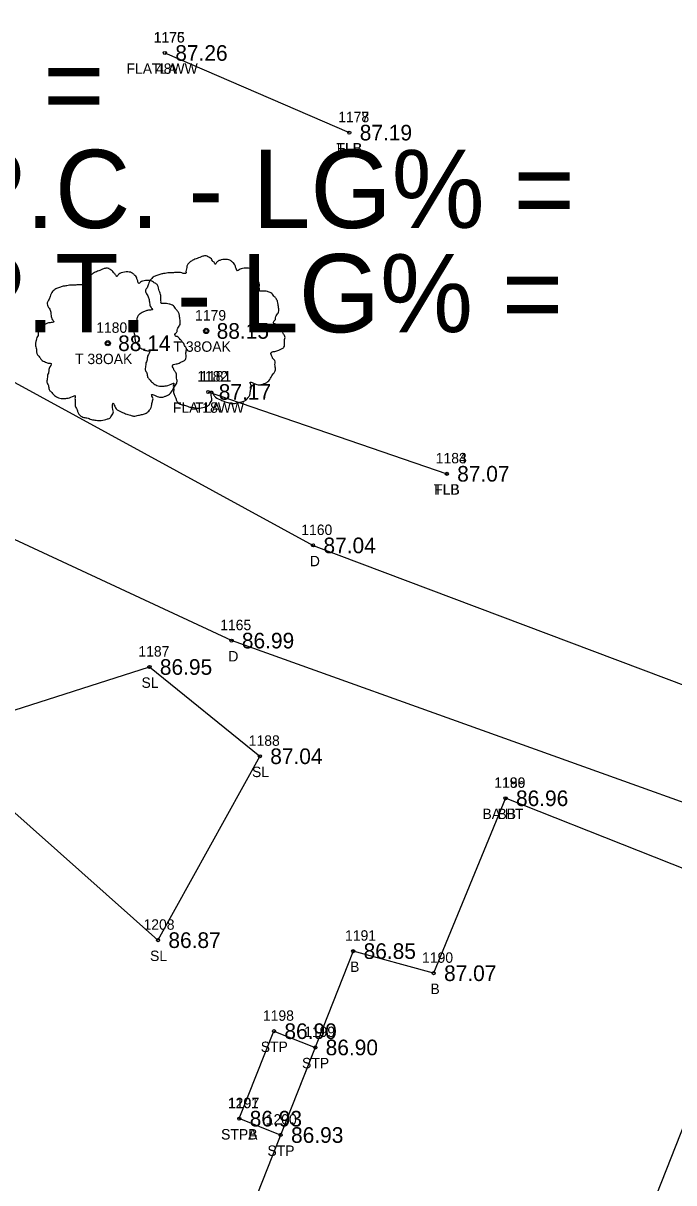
# Model space of a CAD drawing. Extents: x 2139392 to 2143384, y 505395 to 510520.
# Drawn here: x 2141405.4 to 2141467.9, y 510076.4 to 510187.6 of the extents above; entities that cross this region are included whole.
import ezdxf

# ---------------------------------------------------------------- set-up
doc = ezdxf.new("R2010")
doc.units = 0
for name, color, linetype in [('RD_EX_Bldg', 7, 'Continuous'), ('RD_EX_Bldg_txCode', 7, 'Continuous'), ('RD_EX_Conc', 7, 'Continuous'), ('RD_EX_Conc_txCode', 7, 'Continuous'), ('RD_EX_Driveway', 7, 'Continuous'), ('RD_EX_Driveway_txCode', 7, 'Continuous'), ('RD_EX_Fence_Other', 7, 'Continuous'), ('RD_EX_Fence_Other_txCode', 7, 'Continuous'), ('RD_EX_TX_Bldg_ELEV', 7, 'Continuous'), ('RD_EX_TX_Conc_ELEV', 7, 'Continuous'), ('RD_EX_TX_Driveway_ELEV', 7, 'Continuous'), ('RD_EX_TX_Fence_Other_ELEV', 7, 'Continuous'), ('RD_EX_TX_VEG_ELEV', 7, 'Continuous'), ('RD_EX_VEG', 7, 'Continuous'), ('RD_EX_VEG_txCode', 7, 'Continuous'), ('RD_HC_Cl', 7, 'Continuous'), ('RD_HC_Data', 7, 'Continuous'), ('RD_SMD_Locator', 7, 'Continuous')]:
    doc.layers.add(name, color=color, linetype=linetype)

msp = doc.modelspace()

# ---------------------------------------------------------------- linework, layer by layer
at = {"layer": 'RD_EX_Bldg'}
msp.add_lwpolyline([(2141451.72, 510113.31), (2141444.82, 510096.53), (2141437.1, 510098.65), (2141426.42, 510071.61), (2141433.86, 510068.13), (2141459.35, 510057.93), (2141477.25, 510103.22), (2141451.72, 510113.31)], dxfattribs=at)
at = {"layer": 'RD_EX_Conc'}
msp.add_lwpolyline([(2141426.17, 510082.58), (2141429.5, 510090.97), (2141433.46, 510089.41), (2141430.14, 510081.01), (2141426.17, 510082.58)], dxfattribs=at)
at = {"layer": 'RD_EX_Driveway'}
for points in [[(2141397.35, 510157.14), (2141433.25, 510137.56), (2141478.15, 510120.63)], [(2141480.37, 510108.75), (2141425.42, 510128.43), (2141389.73, 510145.03)]]:
    msp.add_lwpolyline(points, dxfattribs=at)
at = {"layer": 'RD_EX_Fence_Other'}
for p, q in [((2141419.03, 510184.79), (2141436.73, 510177.15)), ((2141423.2, 510152.28), (2141446.08, 510144.43))]:
    msp.add_line(p, q, dxfattribs=at)
at = {"layer": 'RD_EX_VEG'}
for p, q in [((2141419.03, 510184.79), (2141436.73, 510177.15)), ((2141423.2, 510152.28), (2141446.08, 510144.43))]:
    msp.add_line(p, q, dxfattribs=at)
msp.add_lwpolyline([(2141396.46, 510119.18), (2141417.55, 510125.9), (2141428.14, 510117.34), (2141418.37, 510099.7), (2141396.46, 510119.18)], dxfattribs=at)
for centre, radius in [((2141423, 510158.13), 0.25), ((2141422.98, 510158.12), 0.0001), ((2141413.55, 510156.95), 0.25), ((2141413.53, 510156.93), 0.0001)]:
    msp.add_circle(centre, radius, dxfattribs=at)
for points in [[(2141423.13, 510165.3), (2141422.83, 510165.33), (2141422.5, 510165.23), (2141422.25, 510165.13), (2141422.03, 510165.05), (2141421.8, 510164.95), (2141421.5, 510164.78), (2141421.28, 510164.58), (2141421.15, 510164.33), (2141421.1, 510164.1), (2141421.05, 510163.83), (2141421.05, 510163.65), (2141420.93, 510163.63), (2141420.78, 510163.65), (2141420.53, 510163.73), (2141420.28, 510163.73), (2141420.03, 510163.73), (2141419.68, 510163.7), (2141419.33, 510163.7), (2141419.05, 510163.65), (2141418.73, 510163.6), (2141418.35, 510163.48), (2141418, 510163.35), (2141417.7, 510163.1), (2141417.45, 510162.63), (2141417.33, 510162.28), (2141417.18, 510162.03), (2141417.33, 510161.58), (2141417.5, 510161.23), (2141417.53, 510161.03), (2141417.6, 510160.6), (2141417.7, 510160.38), (2141417.83, 510160.18), (2141417.75, 510160.15), (2141417.38, 510160.1), (2141417.08, 510160), (2141416.65, 510159.78), (2141416.43, 510159.55), (2141416.33, 510159.23), (2141416.3, 510158.88), (2141416.21, 510158.68), (2141416.13, 510158.4), (2141416.11, 510158.33), (2141416.06, 510158), (2141416.16, 510157.55), (2141416.18, 510157.2), (2141416.3, 510156.98), (2141416.45, 510156.8), (2141416.63, 510156.55), (2141417.03, 510156.33), (2141417.35, 510156.23), (2141417.55, 510156.21), (2141417.38, 510155.71), (2141417.33, 510155.36), (2141417.2, 510154.96), (2141417.2, 510154.88), (2141417.15, 510154.41), (2141417.3, 510154.08), (2141417.38, 510153.71), (2141417.55, 510153.48), (2141417.83, 510153.18), (2141418.15, 510152.96), (2141418.65, 510152.83), (2141419.05, 510152.86), (2141419.63, 510153.03), (2141419.88, 510153.11), (2141419.85, 510152.93), (2141419.88, 510152.56), (2141419.88, 510152.13), (2141420.03, 510151.81), (2141420.13, 510151.53), (2141420.28, 510151.28), (2141420.6, 510151.06), (2141421, 510150.98), (2141421.43, 510150.83), (2141421.88, 510150.76), (2141422.38, 510150.73), (2141422.98, 510150.88), (2141423.25, 510151.01), (2141423.35, 510151.18), (2141423.55, 510151.56), (2141423.5, 510151.78), (2141423.53, 510152.38), (2141423.63, 510152.21), (2141423.8, 510151.86), (2141424.3, 510151.56), (2141424.7, 510151.38), (2141425.18, 510151.23), (2141425.48, 510151.16), (2141425.95, 510151.23), (2141426.33, 510151.31), (2141426.7, 510151.43), (2141427, 510151.71), (2141427.18, 510151.98), (2141427.23, 510152.26), (2141427.3, 510152.63), (2141427.35, 510152.81)], [(2141427.35, 510152.81), (2141427.28, 510152.98), (2141427.23, 510153.23), (2141427.3, 510153.21), (2141427.48, 510153.16), (2141427.75, 510153.03), (2141427.97, 510152.96), (2141428.3, 510152.98), (2141428.57, 510153.08), (2141429.02, 510153.36), (2141429.3, 510153.83), (2141429.57, 510154.23), (2141429.65, 510154.56), (2141429.6, 510154.78), (2141429.57, 510155.28), (2141429.37, 510155.53), (2141429.32, 510155.66), (2141429.22, 510156.06), (2141429.3, 510156.11), (2141429.57, 510156.16), (2141429.95, 510156.28), (2141430.22, 510156.4), (2141430.45, 510156.58), (2141430.52, 510156.8), (2141430.5, 510157.2), (2141430.55, 510157.6), (2141430.47, 510157.75), (2141430.37, 510157.9), (2141430.3, 510158.1), (2141430.15, 510158.25), (2141430.05, 510158.4), (2141429.95, 510158.5), (2141429.82, 510158.65), (2141429.65, 510158.78), (2141429.5, 510158.83), (2141429.45, 510158.98), (2141429.6, 510159.18), (2141429.65, 510159.28), (2141429.67, 510159.5), (2141429.9, 510159.85), (2141429.95, 510160.25), (2141429.9, 510160.68), (2141429.85, 510160.95), (2141429.7, 510161.23), (2141429.5, 510161.48), (2141429.37, 510161.65), (2141429.2, 510161.78), (2141428.87, 510161.9), (2141428.62, 510161.95), (2141428.27, 510161.95), (2141428.07, 510162), (2141428.1, 510162.05), (2141428.1, 510162.2), (2141428.1, 510162.48), (2141428.02, 510162.93), (2141427.87, 510163.43), (2141427.87, 510163.45), (2141427.77, 510163.7), (2141427.55, 510163.9), (2141427.38, 510164), (2141427.18, 510164.13), (2141426.93, 510164.15), (2141426.63, 510164.15), (2141426.35, 510164.1), (2141426.15, 510164), (2141425.98, 510163.88), (2141425.9, 510164.03), (2141425.8, 510164.33), (2141425.75, 510164.48), (2141425.6, 510164.65), (2141425.38, 510164.85), (2141424.93, 510164.98), (2141424.3, 510164.9), (2141424, 510164.7), (2141423.85, 510164.53), (2141423.8, 510164.65), (2141423.6, 510164.85), (2141423.5, 510165.03), (2141423.33, 510165.15), (2141423.18, 510165.25), (2141423.08, 510165.3)], [(2141413.68, 510164.11), (2141413.38, 510164.14), (2141413.05, 510164.04), (2141412.8, 510163.94), (2141412.58, 510163.86), (2141412.35, 510163.76), (2141412.05, 510163.59), (2141411.83, 510163.39), (2141411.7, 510163.14), (2141411.65, 510162.91), (2141411.6, 510162.64), (2141411.6, 510162.46), (2141411.48, 510162.44), (2141411.33, 510162.46), (2141411.08, 510162.54), (2141410.83, 510162.54), (2141410.58, 510162.54), (2141410.23, 510162.51), (2141409.88, 510162.51), (2141409.61, 510162.46), (2141409.28, 510162.41), (2141408.91, 510162.29), (2141408.56, 510162.16), (2141408.26, 510161.91), (2141408.01, 510161.44), (2141407.88, 510161.09), (2141407.73, 510160.84), (2141407.88, 510160.39), (2141408.06, 510160.04), (2141408.08, 510159.84), (2141408.16, 510159.41), (2141408.26, 510159.19), (2141408.38, 510158.99), (2141408.31, 510158.96), (2141407.93, 510158.91), (2141407.63, 510158.81), (2141407.21, 510158.59), (2141406.98, 510158.37), (2141406.88, 510158.04), (2141406.86, 510157.69), (2141406.76, 510157.49), (2141406.68, 510157.22), (2141406.66, 510157.14), (2141406.61, 510156.82), (2141406.71, 510156.37), (2141406.73, 510156.02), (2141406.86, 510155.79), (2141407.01, 510155.62), (2141407.18, 510155.37), (2141407.58, 510155.14), (2141407.91, 510155.04), (2141408.11, 510155.02), (2141407.93, 510154.52), (2141407.88, 510154.17), (2141407.76, 510153.77), (2141407.76, 510153.69), (2141407.71, 510153.22), (2141407.86, 510152.89), (2141407.93, 510152.52), (2141408.11, 510152.29), (2141408.38, 510151.99), (2141408.71, 510151.77), (2141409.21, 510151.64), (2141409.61, 510151.67), (2141410.18, 510151.84), (2141410.43, 510151.92), (2141410.41, 510151.74), (2141410.43, 510151.37), (2141410.43, 510150.94), (2141410.58, 510150.62), (2141410.68, 510150.34), (2141410.83, 510150.09), (2141411.15, 510149.87), (2141411.55, 510149.79), (2141411.98, 510149.64), (2141412.43, 510149.57), (2141412.93, 510149.54), (2141413.53, 510149.69), (2141413.8, 510149.82), (2141413.9, 510149.99), (2141414.1, 510150.37), (2141414.05, 510150.59), (2141414.08, 510151.19), (2141414.18, 510151.02), (2141414.35, 510150.67), (2141414.85, 510150.37), (2141415.25, 510150.19), (2141415.73, 510150.04), (2141416.03, 510149.97), (2141416.5, 510150.04), (2141416.88, 510150.12), (2141417.25, 510150.24), (2141417.55, 510150.52), (2141417.73, 510150.79), (2141417.78, 510151.07), (2141417.85, 510151.44), (2141417.9, 510151.62)], [(2141417.9, 510151.62), (2141417.83, 510151.79), (2141417.78, 510152.04), (2141417.85, 510152.02), (2141418.03, 510151.97), (2141418.3, 510151.84), (2141418.53, 510151.77), (2141418.85, 510151.79), (2141419.13, 510151.89), (2141419.58, 510152.17), (2141419.85, 510152.64), (2141420.13, 510153.04), (2141420.2, 510153.37), (2141420.15, 510153.59), (2141420.13, 510154.09), (2141419.93, 510154.34), (2141419.88, 510154.47), (2141419.78, 510154.87), (2141419.85, 510154.92), (2141420.13, 510154.97), (2141420.5, 510155.09), (2141420.78, 510155.22), (2141421, 510155.39), (2141421.08, 510155.62), (2141421.05, 510156.02), (2141421.1, 510156.42), (2141421.03, 510156.57), (2141420.93, 510156.72), (2141420.85, 510156.92), (2141420.7, 510157.07), (2141420.6, 510157.22), (2141420.5, 510157.32), (2141420.38, 510157.47), (2141420.2, 510157.59), (2141420.05, 510157.64), (2141420, 510157.79), (2141420.15, 510157.99), (2141420.2, 510158.09), (2141420.23, 510158.32), (2141420.45, 510158.66), (2141420.5, 510159.06), (2141420.45, 510159.49), (2141420.4, 510159.76), (2141420.25, 510160.04), (2141420.05, 510160.29), (2141419.93, 510160.46), (2141419.75, 510160.59), (2141419.43, 510160.71), (2141419.18, 510160.76), (2141418.83, 510160.76), (2141418.63, 510160.81), (2141418.65, 510160.86), (2141418.65, 510161.01), (2141418.65, 510161.29), (2141418.58, 510161.74), (2141418.43, 510162.24), (2141418.43, 510162.26), (2141418.33, 510162.51), (2141418.1, 510162.71), (2141417.93, 510162.81), (2141417.73, 510162.94), (2141417.48, 510162.96), (2141417.18, 510162.96), (2141416.9, 510162.91), (2141416.7, 510162.81), (2141416.53, 510162.69), (2141416.45, 510162.84), (2141416.35, 510163.14), (2141416.3, 510163.29), (2141416.15, 510163.46), (2141415.93, 510163.66), (2141415.48, 510163.79), (2141414.85, 510163.71), (2141414.55, 510163.51), (2141414.4, 510163.34), (2141414.35, 510163.46), (2141414.15, 510163.66), (2141414.05, 510163.84), (2141413.88, 510163.96), (2141413.73, 510164.06), (2141413.63, 510164.11)]]:
    msp.add_spline(points, degree=3, dxfattribs=at)
at = {"layer": 'RD_HC_Cl'}
msp.add_arc((2138642.96, 511065.46), 2864.78, 339.91581, 348.5415, dxfattribs=at)
at = {"layer": 'RD_SMD_Locator'}
for centre in [(2141419.03, 510184.79), (2141419.03, 510184.79), (2141436.73, 510177.15), (2141436.73, 510177.15), (2141423, 510158.13), (2141413.55, 510156.95), (2141423.2, 510152.28), (2141423.2, 510152.28), (2141446.08, 510144.43), (2141446.08, 510144.43), (2141433.25, 510137.56), (2141425.42, 510128.43), (2141417.55, 510125.9), (2141428.14, 510117.34), (2141451.72, 510113.31), (2141451.72, 510113.31), (2141418.37, 510099.7), (2141437.1, 510098.65), (2141444.82, 510096.53), (2141429.5, 510090.97), (2141433.46, 510089.41), (2141426.17, 510082.58), (2141426.17, 510082.58), (2141430.14, 510081.01)]:
    msp.add_circle(centre, 0.15, dxfattribs=at)

# ---------------------------------------------------------------- texts
at = {"layer": 'RD_EX_Bldg_txCode'}
for s, p in [('1196', (2141450.63, 510114.31)), ('1189', (2141450.65, 510114.31)), ('BA HT', (2141449.5, 510111.31)), ('BB', (2141450.94, 510111.31)), ('1191', (2141436.32, 510099.65)), ('B', (2141436.8, 510096.65)), ('1190', (2141443.71, 510097.53)), ('B', (2141444.51, 510094.53))]:
    msp.add_text(s, height=1, dxfattribs=at).set_placement(p)
at = {"layer": 'RD_EX_Conc_txCode'}
for s, p in [('1198', (2141428.44, 510091.97)), ('1199', (2141432.39, 510090.41)), ('STP', (2141428.23, 510088.97)), ('STP', (2141432.19, 510087.41)), ('1201', (2141425.07, 510083.58)), ('1197', (2141425.11, 510083.58)), ('1200', (2141428.71, 510082.01)), ('STPA', (2141424.42, 510080.58)), ('STPB', (2141424.43, 510080.58)), ('STP', (2141428.87, 510079.01))]:
    msp.add_text(s, height=1, dxfattribs=at).set_placement(p)
at = {"layer": 'RD_EX_Driveway_txCode'}
for s, p in [('1160', (2141432.12, 510138.56)), ('D', (2141432.94, 510135.56)), ('1165', (2141424.34, 510129.43)), ('D', (2141425.12, 510126.43))]:
    msp.add_text(s, height=1, dxfattribs=at).set_placement(p)
at = {"layer": 'RD_EX_Fence_Other_txCode'}
for s, p in [('1175', (2141417.97, 510185.79)), ('FLA 48WW', (2141415.35, 510182.79)), ('1178', (2141435.66, 510178.15)), ('FLB', (2141435.52, 510175.15)), ('1181', (2141422.42, 510153.28)), ('FLA 18WW', (2141419.8, 510150.28)), ('1184', (2141445.02, 510145.43)), ('FLB', (2141444.88, 510142.43))]:
    msp.add_text(s, height=1, dxfattribs=at).set_placement(p)
at = {"layer": 'RD_EX_TX_Bldg_ELEV'}
for s, p in [('86.96', (2141452.72, 510112.56)), ('86.96', (2141452.72, 510112.56)), ('86.85', (2141438.1, 510097.9)), ('87.07', (2141445.82, 510095.78))]:
    msp.add_text(s, height=1.5, dxfattribs=at).set_placement(p)
at = {"layer": 'RD_EX_TX_Conc_ELEV'}
for s, p in [('86.90', (2141430.5, 510090.22)), ('86.90', (2141434.46, 510088.66)), ('86.93', (2141427.17, 510081.83)), ('86.93', (2141427.17, 510081.83)), ('86.93', (2141431.14, 510080.26))]:
    msp.add_text(s, height=1.5, dxfattribs=at).set_placement(p)
at = {"layer": 'RD_EX_TX_Driveway_ELEV'}
for s, p in [('87.04', (2141434.25, 510136.81)), ('86.99', (2141426.42, 510127.68))]:
    msp.add_text(s, height=1.5, dxfattribs=at).set_placement(p)
at = {"layer": 'RD_EX_TX_Fence_Other_ELEV'}
for s, p in [('87.26', (2141420.03, 510184.04)), ('87.19', (2141437.73, 510176.4)), ('87.17', (2141424.2, 510151.53)), ('87.07', (2141447.08, 510143.68))]:
    msp.add_text(s, height=1.5, dxfattribs=at).set_placement(p)
at = {"layer": 'RD_EX_TX_VEG_ELEV'}
for s, p in [('87.26', (2141420.03, 510184.04)), ('87.19', (2141437.73, 510176.4)), ('88.15', (2141424, 510157.38)), ('88.14', (2141414.55, 510156.2)), ('87.17', (2141424.2, 510151.53)), ('87.07', (2141447.08, 510143.68)), ('86.95', (2141418.55, 510125.15)), ('87.04', (2141429.14, 510116.59)), ('86.87', (2141419.37, 510098.95))]:
    msp.add_text(s, height=1.5, dxfattribs=at).set_placement(p)
at = {"layer": 'RD_EX_VEG_txCode'}
for s, p in [('1176', (2141417.95, 510185.79)), ('TLA', (2141417.77, 510182.79)), ('1177', (2141435.66, 510178.15)), ('TLB', (2141435.48, 510175.15)), ('1179', (2141421.93, 510159.13)), ('1180', (2141412.44, 510157.95)), ('T 38OAK', (2141419.86, 510156.13)), ('T 38OAK', (2141410.41, 510154.95)), ('1182', (2141422.13, 510153.28)), ('TLA', (2141421.94, 510150.28)), ('1183', (2141445.02, 510145.43)), ('TLB', (2141444.84, 510142.43)), ('1187', (2141416.49, 510126.9)), ('SL', (2141416.79, 510123.9)), ('1188', (2141427.08, 510118.34)), ('SL', (2141427.39, 510115.34)), ('1208', (2141416.98, 510100.7)), ('SL', (2141417.61, 510097.7))]:
    msp.add_text(s, height=1, dxfattribs=at).set_placement(p)
at = {"layer": 'RD_HC_Data'}
for s, p in [('e = ', (2141399, 510178)), ('P.C. - LG% = ', (2141399, 510168)), ('P.T. - LG% = ', (2141399, 510158))]:
    msp.add_text(s, height=7.5, dxfattribs=at).set_placement(p)

doc.saveas('drawing.dxf')
